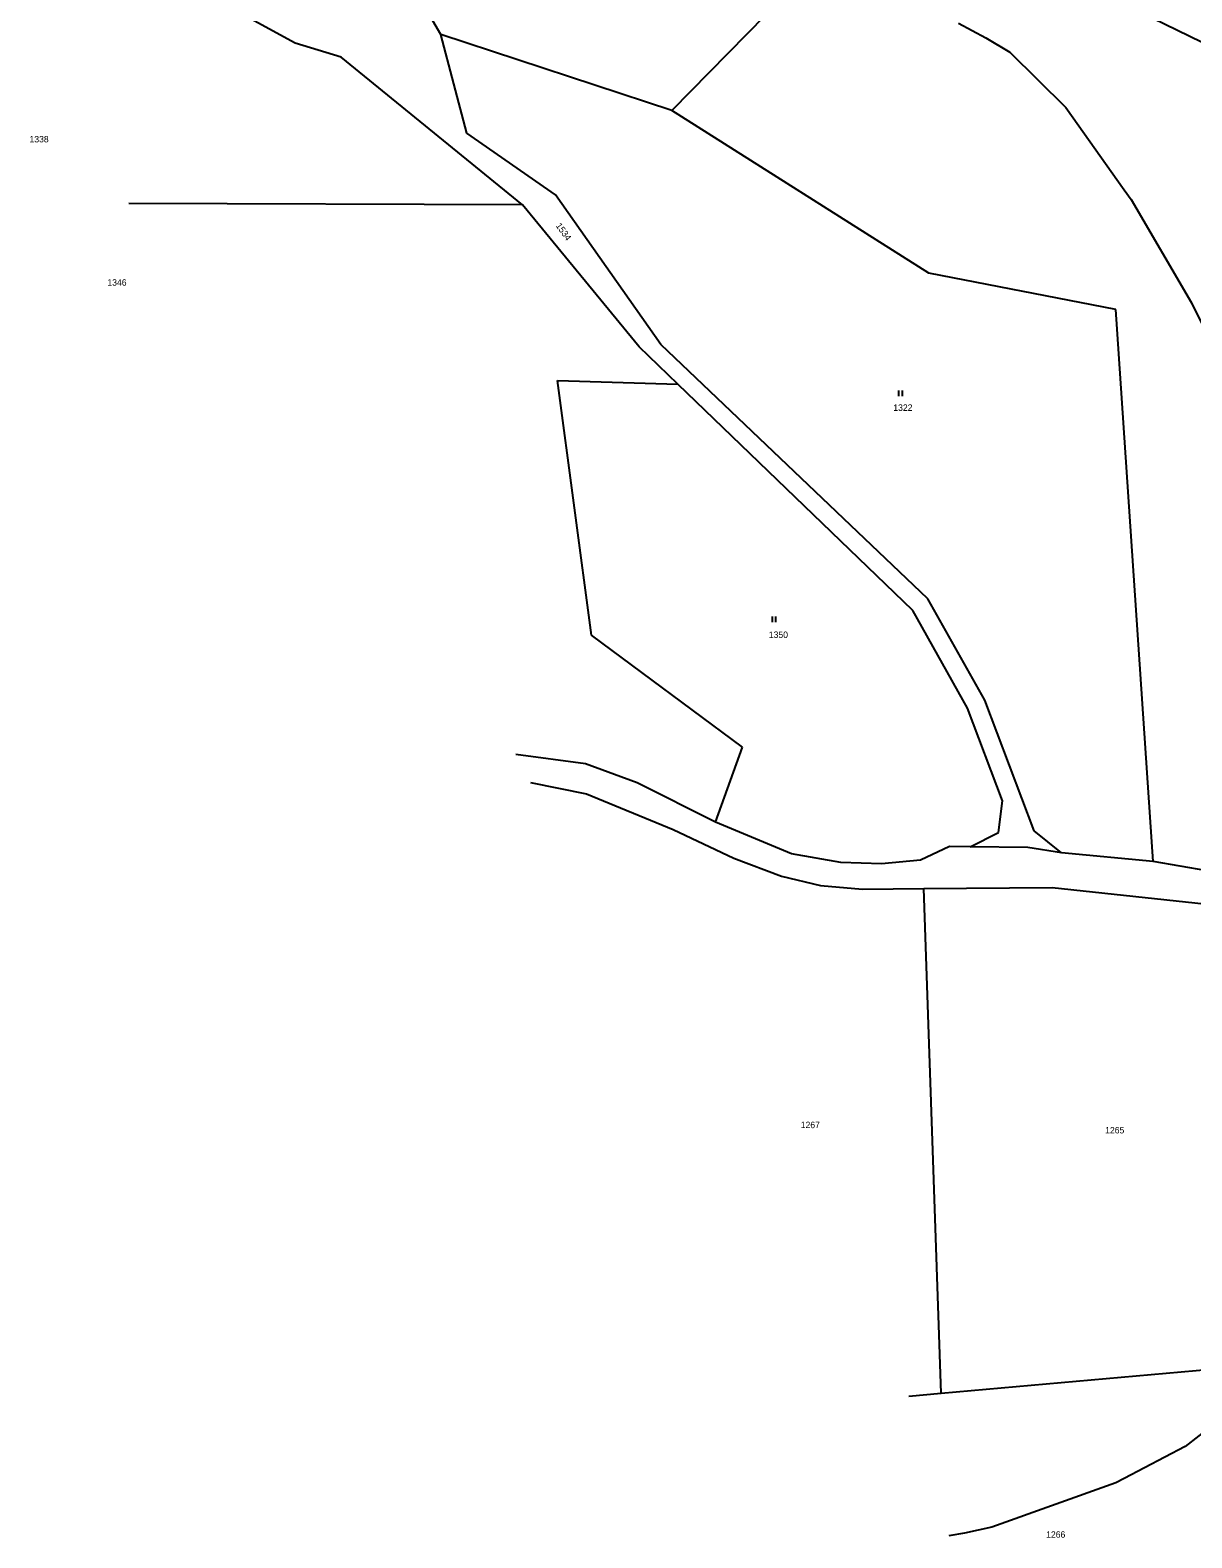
# Model space of a CAD drawing. Extents: x -792913 to -792113, y -1112764 to -1111548.
# Drawn here: x -792731.9 to -792425.8, y -1112737.1 to -1112340 of the extents above; entities that cross this region are included whole.
import ezdxf

# ---------------------------------------------------------------- set-up
doc = ezdxf.new("R2010")
doc.units = 0
for name, color, linetype in [('Vrstva 1', 7, 'Continuous'), ('Vrstva 11', 7, 'Continuous'), ('Vrstva 2', 7, 'Continuous'), ('Vrstva 3', 7, 'Continuous')]:
    doc.layers.add(name, color=color, linetype=linetype)

msp = doc.modelspace()

# ---------------------------------------------------------------- linework, layer by layer
at = {"layer": 'Vrstva 1'}
for p, q in [((-792497.31, -1112294.38), (-792562.85, -1112361.21)), ((-792662.04, -1112343.48), (-792683.47, -1112331.71)), ((-792623.71, -1112341.2), (-792627.65, -1112334.38)), ((-792436.12, -1112336.84), (-792391.37, -1112358.8)), ((-792562.85, -1112361.21), (-792623.71, -1112341.2)), ((-792616.87, -1112367.14), (-792623.71, -1112341.2)), ((-792649.99, -1112347.1), (-792662.04, -1112343.48)), ((-792662.04, -1112343.48), (-792662.04, -1112343.48)), ((-792602.14, -1112386), (-792649.99, -1112347.1)), ((-792495.14, -1112404.02), (-792562.85, -1112361.21)), ((-792593.49, -1112383.44), (-792616.87, -1112367.14)), ((-792602.14, -1112386), (-792705.91, -1112385.69)), ((-792571.43, -1112423.45), (-792602.14, -1112386)), ((-792565.75, -1112422.82), (-792593.49, -1112383.44)), ((-792445.91, -1112413.56), (-792495.14, -1112404.02)), ((-792436.08, -1112559.01), (-792445.91, -1112413.56)), ((-792561.24, -1112433.27), (-792571.43, -1112423.45)), ((-792495.37, -1112489.79), (-792565.75, -1112422.82)), ((-792592.95, -1112432.33), (-792561.24, -1112433.27)), ((-792584.02, -1112499.33), (-792592.95, -1112432.33)), ((-792592.95, -1112432.33), (-792592.95, -1112432.33)), ((-792499.35, -1112492.9), (-792561.24, -1112433.27)), ((-792480.38, -1112516.44), (-792495.37, -1112489.79)), ((-792484.92, -1112518.55), (-792499.35, -1112492.9)), ((-792544.23, -1112528.87), (-792584.02, -1112499.33)), ((-792467.39, -1112550.93), (-792480.38, -1112516.44)), ((-792475.74, -1112542.95), (-792484.92, -1112518.55)), ((-792551.36, -1112548.61), (-792544.23, -1112528.87)), ((-792585.55, -1112533.29), (-792603.9, -1112530.75)), ((-792572.01, -1112538.26), (-792585.55, -1112533.29)), ((-792600.09, -1112538.16), (-792585.32, -1112541.12)), ((-792585.32, -1112541.12), (-792562.5, -1112550.5)), ((-792551.36, -1112548.61), (-792572.01, -1112538.26)), ((-792476.8, -1112551.29), (-792475.74, -1112542.95)), ((-792531.31, -1112556.91), (-792551.36, -1112548.61)), ((-792562.5, -1112550.5), (-792546.47, -1112558.06)), ((-792562.5, -1112550.5), (-792562.5, -1112550.5)), ((-792484.29, -1112555.12), (-792476.8, -1112551.29)), ((-792460.23, -1112556.67), (-792467.39, -1112550.93)), ((-792518.33, -1112559.25), (-792531.31, -1112556.91)), ((-792489.67, -1112555.04), (-792497.33, -1112558.59)), ((-792484.29, -1112555.12), (-792489.67, -1112555.04)), ((-792469.1, -1112555.26), (-792484.29, -1112555.12)), ((-792460.23, -1112556.67), (-792469.1, -1112555.26)), ((-792436.08, -1112559.01), (-792460.23, -1112556.67)), ((-792546.47, -1112558.06), (-792533.95, -1112562.84)), ((-792507.58, -1112559.55), (-792518.33, -1112559.25)), ((-792497.33, -1112558.59), (-792507.58, -1112559.55)), ((-792421.78, -1112561.41), (-792436.08, -1112559.01)), ((-792533.95, -1112562.84), (-792523.68, -1112565.29)), ((-792523.68, -1112565.29), (-792512.62, -1112566.27)), ((-792512.62, -1112566.27), (-792496.46, -1112566.12)), ((-792496.46, -1112566.12), (-792462.63, -1112565.81)), ((-792491.89, -1112698.99), (-792496.46, -1112566.12)), ((-792462.63, -1112565.81), (-792419.39, -1112570.47)), ((-792491.89, -1112698.99), (-792396.23, -1112690.52)), ((-792500.45, -1112699.75), (-792491.89, -1112698.99)), ((-792500.45, -1112699.75), (-792500.45, -1112699.75)), ((-792500.45, -1112699.75), (-792500.45, -1112699.75))]:
    msp.add_line(p, q, dxfattribs=at)
at = {"layer": 'Vrstva 11'}
for p, q in [((-792487.32, -1112338.15), (-792480.14, -1112342.01)), ((-792480.14, -1112342.01), (-792473.81, -1112345.87)), ((-792473.81, -1112345.87), (-792459.08, -1112360.37)), ((-792459.08, -1112360.37), (-792443.66, -1112382.07)), ((-792443.66, -1112382.07), (-792441.85, -1112384.62)), ((-792441.85, -1112384.62), (-792425.92, -1112411.82)), ((-792425.92, -1112411.82), (-792417.97, -1112427.96)), ((-792413.18, -1112701.74), (-792427.64, -1112713.05)), ((-792427.64, -1112713.05), (-792443.66, -1112721.46)), ((-792445.9, -1112722.64), (-792478.58, -1112734.24)), ((-792443.66, -1112721.46), (-792445.9, -1112722.64)), ((-792485.78, -1112735.88), (-792489.87, -1112736.58)), ((-792482.18, -1112735.06), (-792485.78, -1112735.88)), ((-792478.58, -1112734.24), (-792482.18, -1112735.06))]:
    msp.add_line(p, q, dxfattribs=at)
at = {"layer": 'Vrstva 3'}
for p, q in [((-792503.09, -1112434.91), (-792503.09, -1112436.41)), ((-792502.09, -1112436.41), (-792502.09, -1112434.91)), ((-792536.44, -1112494.44), (-792536.44, -1112495.94)), ((-792535.44, -1112495.94), (-792535.44, -1112494.44))]:
    msp.add_line(p, q, dxfattribs=at)

# ---------------------------------------------------------------- texts
at = {"layer": 'Vrstva 2'}
for s, p in [('1338', (-792732.057, -1112369.59)), ('1346', (-792711.537, -1112407.32)), ('1322', (-792504.497, -1112440.29)), ('1350', (-792537.297, -1112500.1)), ('1267', (-792528.887, -1112629.19)), ('1265', (-792448.697, -1112630.58)), ('1266', (-792464.237, -1112737.06))]:
    msp.add_text(s, height=1.7, dxfattribs=at).set_placement(p)
msp.add_text('1534', height=1.7, rotation=305.95946, dxfattribs=at).set_placement((-792593.519, -1112391.558))

doc.saveas('drawing.dxf')
